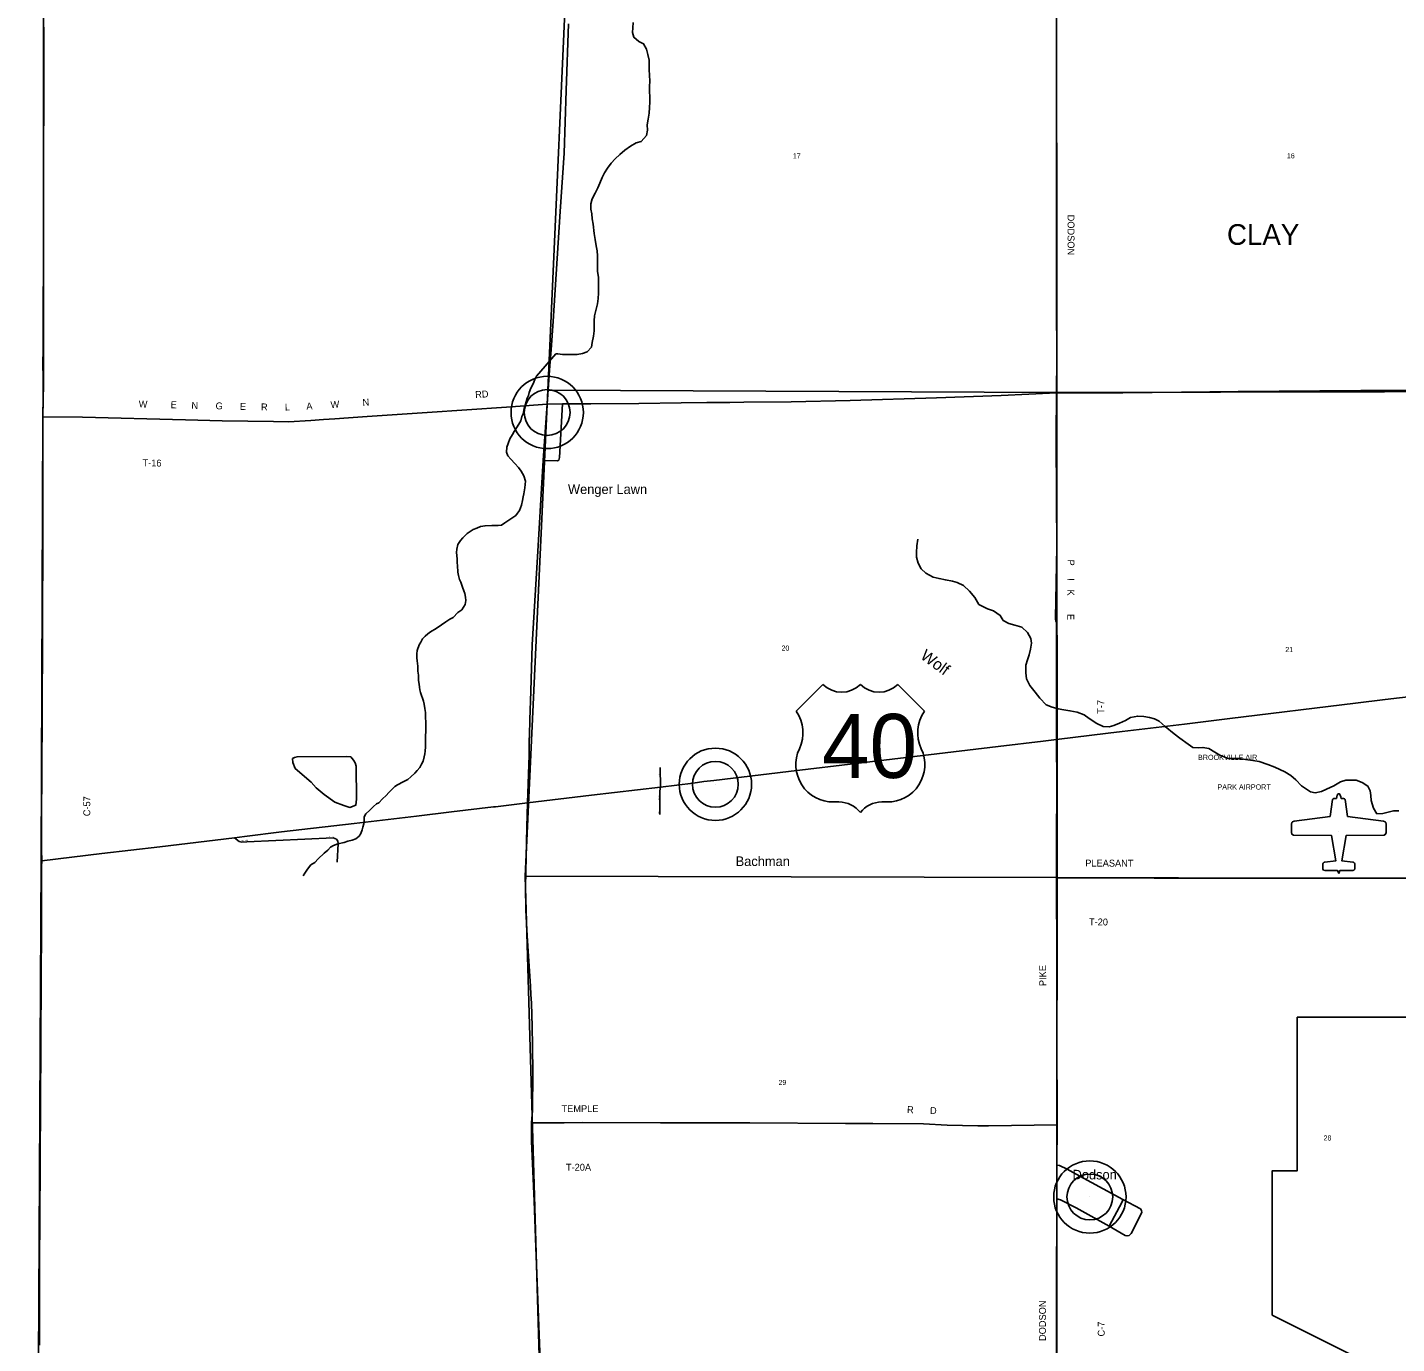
# Model space of a CAD drawing. Extents: x 1312308 to 1684953, y 460642 to 865172.
# Drawn here: x 1411378 to 1426256, y 678293 to 692598 of the extents above; entities that cross this region are included whole.
import ezdxf

# ---------------------------------------------------------------- set-up
doc = ezdxf.new("R2010")
doc.units = 0
for name, color, linetype in [('GM_X_Adjacent_County', 7, 'Continuous'), ('GM_X_Airport_Class_3', 7, 'Continuous'), ('GM_X_Airport_Location_Class_3', 7, 'Continuous'), ('GM_X_Airport_Text_Class_3', 7, 'Continuous'), ('GM_X_Corporation', 7, 'Continuous'), ('GM_X_County', 7, 'Continuous'), ('GM_X_County_Road', 7, 'Continuous'), ('GM_X_County_Road_Text', 7, 'Continuous'), ('GM_X_Minor_Lake', 7, 'Continuous'), ('GM_X_Minor_River', 7, 'Continuous'), ('GM_X_Minor_River_Text', 7, 'Continuous'), ('GM_X_Section', 7, 'Continuous'), ('GM_X_Section_Text', 7, 'Continuous'), ('GM_X_Township', 7, 'Continuous'), ('GM_X_Township_Road', 7, 'Continuous'), ('GM_X_Township_Road_Text', 7, 'Continuous'), ('GM_X_Township_Subdivision', 7, 'Continuous'), ('GM_X_Township_Subdivision_Text', 7, 'Continuous'), ('GM_X_Township_Text', 7, 'Continuous'), ('GM_X_Unincorporated', 7, 'Continuous'), ('GM_X_Unincorporated_Location', 7, 'Continuous'), ('GM_X_Unincorporated_Text', 7, 'Continuous'), ('GM_X_US_Location', 7, 'Continuous'), ('GM_X_US_Route', 7, 'Continuous'), ('GM_X_US_Shield', 7, 'Continuous')]:
    doc.layers.add(name, color=color, linetype=linetype)

msp = doc.modelspace()

# ---------------------------------------------------------------- linework, layer by layer
at = {"layer": 'GM_X_Adjacent_County'}
msp.add_lwpolyline([(1411554, 694026), (1411551, 688725), (1411547, 688368), (1411526, 683541), (1411498, 678086), (1411466, 675468), (1411467, 672788), (1411460, 671583), (1411440, 668150), (1411439, 668011), (1411421, 665395), (1411387, 659976), (1411378, 657454)], dxfattribs=at)
at = {"layer": 'GM_X_Airport_Class_3'}
for points in [[(1425628, 684270), (1425621, 684267), (1425612, 684255), (1425606, 684237), (1425603, 684219), (1425576, 684219), (1425566, 684215), (1425560, 684207), (1425534, 684023), (1425142, 683973), (1425125, 683965), (1425119, 683958), (1425113, 683940), (1425113, 683849), (1425119, 683830), (1425136, 683818), (1425549, 683815), (1425597, 683541), (1425475, 683527), (1425468, 683525), (1425457, 683516), (1425454, 683509), (1425453, 683459), (1425454, 683451), (1425463, 683439), (1425478, 683434), (1425615, 683434), (1425628, 683402)], [(1425628, 683402), (1425641, 683434), (1425779, 683434), (1425793, 683439), (1425802, 683451), (1425803, 683459), (1425802, 683509), (1425799, 683516), (1425788, 683525), (1425781, 683527), (1425660, 683541), (1425708, 683815), (1426121, 683818), (1426137, 683830), (1426144, 683849), (1426143, 683940), (1426138, 683958), (1426132, 683965), (1426114, 683973), (1425723, 684023), (1425696, 684207), (1425691, 684215), (1425680, 684219), (1425653, 684219), (1425650, 684237), (1425644, 684255), (1425636, 684267), (1425628, 684270)]]:
    msp.add_lwpolyline(points, dxfattribs=at)
at = {"layer": 'GM_X_Airport_Location_Class_3'}
msp.add_line((1425628, 683860), (1425628, 683860), dxfattribs=at)
at = {"layer": 'GM_X_Corporation'}
msp.add_lwpolyline([(1426321, 678047), (1426075, 678047), (1425962, 678149), (1425788, 678160), (1424905, 678604), (1424905, 680172), (1425177, 680172), (1425176, 681841), (1427466, 681840)], dxfattribs=at)
at = {"layer": 'GM_X_County'}
msp.add_lwpolyline([(1411378, 657454), (1411387, 659976), (1411421, 665395), (1411439, 668011), (1411440, 668150), (1411460, 671583), (1411467, 672788), (1411466, 675468), (1411498, 678086), (1411526, 683541), (1411547, 688368), (1411551, 688725), (1411554, 694026)], dxfattribs=at)
at = {"layer": 'GM_X_County_Road'}
for points in [[(1416954, 678016), (1416921, 678865), (1416904, 679342), (1416884, 679840), (1416856, 680494), (1416857, 680694), (1416867, 680827), (1416869, 681236), (1416866, 681531), (1416864, 681740), (1416855, 681993), (1416850, 682089), (1416844, 682179), (1416826, 682450), (1416809, 682724), (1416794, 683003), (1416790, 683256), (1416805, 683906), (1416814, 684171), (1416830, 684687), (1416832, 684851), (1416834, 684906), (1416838, 685073), (1416848, 685386), (1416862, 685889), (1416921, 686846), (1416975, 687772), (1416984, 687890), (1416999, 688152), (1417026, 688504), (1417056, 688924), (1417068, 689094), (1417090, 689407), (1417166, 690597), (1417211, 691233), (1417234, 691914), (1417256, 692638)], [(1411534, 683542), (1411534, 683558), (1411534, 683572), (1411533, 683593), (1411532, 683603), (1411532, 683612), (1411532, 683650), (1411532, 683849), (1411532, 684007), (1411532, 684205), (1411533, 684324), (1411534, 684491), (1411535, 684644), (1411536, 684758), (1411537, 684895), (1411538, 685152), (1411538, 685253), (1411539, 685348), (1411540, 685495), (1411541, 685644), (1411541, 685704), (1411542, 685861), (1411543, 686072), (1411542, 686278), (1411543, 686478), (1411544, 686686), (1411544, 686837), (1411544, 687002), (1411544, 687046), (1411544, 687232), (1411545, 687436), (1411544, 687738), (1411544, 687910), (1411544, 688155), (1411546, 688367), (1411546, 688397), (1411548, 688552), (1411548, 688664), (1411548, 688727), (1411548, 688761), (1411547, 688974), (1411548, 689064), (1411548, 689266), (1411549, 689464), (1411550, 689735), (1411551, 689836), (1411552, 690019), (1411553, 690157), (1411553, 690277), (1411554, 690473), (1411554, 690678), (1411554, 690772), (1411554, 690891), (1411554, 690991), (1411553, 691150), (1411553, 691262), (1411553, 691405), (1411555, 691648), (1411556, 691810), (1411556, 691982), (1411556, 692267), (1411556, 692344), (1411556, 692426), (1411557, 692600)], [(1422561, 683356), (1422561, 683745), (1422563, 684363), (1422562, 684860)], [(1411508, 678276), (1411508, 678436), (1411508, 678468), (1411509, 678624), (1411509, 678699), (1411509, 678914), (1411509, 679044), (1411510, 679143), (1411511, 679294), (1411512, 679543), (1411513, 679697), (1411514, 679883), (1411515, 680024), (1411516, 680191), (1411517, 680321), (1411518, 680450), (1411518, 680561), (1411519, 680637), (1411520, 680844), (1411521, 681029), (1411522, 681181), (1411523, 681276), (1411523, 681382), (1411524, 681488), (1411524, 681664), (1411525, 681773), (1411525, 681880), (1411526, 681953), (1411526, 682098), (1411527, 682209), (1411528, 682283), (1411529, 682459), (1411530, 682607), (1411531, 682803), (1411532, 682960), (1411532, 683172), (1411532, 683291), (1411532, 683447), (1411532, 683473), (1411532, 683488), (1411532, 683495), (1411532, 683501), (1411532, 683508), (1411533, 683515), (1411533, 683524), (1411534, 683542)], [(1422564, 678007), (1422566, 678768), (1422564, 679455), (1422563, 679532), (1422566, 679868), (1422566, 680232), (1422568, 680673), (1422566, 681655), (1422564, 682449), (1422561, 683356)]]:
    msp.add_lwpolyline(points, dxfattribs=at)
at = {"layer": 'GM_X_Minor_Lake'}
for points in [[(1414954, 684212), (1414952, 684571), (1414940, 684604), (1414921, 684636), (1414892, 684669), (1414841, 684676), (1414309, 684672), (1414281, 684664), (1414259, 684651), (1414262, 684610), (1414288, 684544)], [(1414288, 684544), (1414460, 684394), (1414517, 684334), (1414601, 684260), (1414718, 684179), (1414816, 684143), (1414883, 684120), (1414946, 684144), (1414954, 684212)]]:
    msp.add_lwpolyline(points, dxfattribs=at)
at = {"layer": 'GM_X_Minor_River'}
for points in [[(1417962, 692651), (1417956, 692595), (1417954, 692541), (1417966, 692491), (1418022, 692446), (1418074, 692420), (1418104, 692361), (1418121, 692302), (1418133, 692243), (1418133, 692189), (1418135, 692133), (1418139, 692082), (1418140, 692012), (1418138, 691958), (1418138, 691906), (1418140, 691840), (1418140, 691785), (1418139, 691727), (1418133, 691665), (1418123, 691601), (1418112, 691539), (1418116, 691481), (1418106, 691425), (1418047, 691357), (1417994, 691343), (1417932, 691307), (1417870, 691264), (1417814, 691218), (1417764, 691171), (1417720, 691121), (1417682, 691070), (1417649, 691017), (1417623, 690966), (1417597, 690905), (1417577, 690853), (1417546, 690798), (1417516, 690735), (1417502, 690681), (1417501, 690621), (1417512, 690571), (1417515, 690516), (1417525, 690460), (1417538, 690359), (1417549, 690294), (1417558, 690224), (1417570, 690169), (1417572, 690117), (1417574, 690060), (1417572, 689998), (1417574, 689946), (1417582, 689885), (1417585, 689821), (1417585, 689767), (1417583, 689709), (1417579, 689653), (1417572, 689595), (1417541, 689465), (1417535, 689409), (1417537, 689351), (1417535, 689299), (1417529, 689241), (1417516, 689175), (1417506, 689123), (1417462, 689071), (1417409, 689055), (1417352, 689045), (1417298, 689045), (1417243, 689043), (1417191, 689045), (1417141, 689051), (1417119, 689052)], [(1417119, 689052), (1416910, 688809), (1416893, 688771), (1416872, 688724), (1416848, 688676), (1416831, 688631), (1416822, 688597), (1416808, 688567), (1416792, 688505), (1416781, 688473), (1416764, 688400), (1416749, 688368), (1416738, 688324), (1416717, 688285), (1416694, 688245), (1416669, 688208), (1416648, 688172), (1416621, 688125), (1416601, 688075), (1416586, 688035), (1416583, 687981), (1416600, 687943), (1416631, 687906), (1416674, 687859), (1416713, 687814), (1416744, 687775), (1416771, 687724), (1416790, 687668), (1416784, 687594), (1416772, 687530), (1416766, 687498), (1416759, 687456), (1416747, 687406), (1416737, 687376), (1416724, 687349), (1416705, 687319), (1416684, 687292), (1416652, 687272), (1416609, 687243), (1416566, 687212), (1416528, 687187), (1416494, 687186), (1416455, 687185), (1416423, 687184), (1416351, 687182), (1416303, 687173), (1416260, 687154), (1416222, 687143), (1416155, 687098), (1416108, 687049), (1416085, 687022), (1416056, 686978), (1416045, 686927), (1416042, 686893), (1416043, 686857), (1416048, 686818), (1416049, 686778), (1416052, 686750), (1416056, 686678), (1416064, 686640), (1416075, 686599), (1416086, 686569), (1416107, 686516), (1416120, 686474), (1416131, 686446), (1416140, 686407), (1416143, 686371), (1416134, 686325), (1416097, 686268), (1416054, 686241), (1416004, 686184), (1415970, 686167), (1415923, 686138), (1415878, 686105), (1415819, 686067), (1415758, 686030), (1415730, 686007), (1415701, 685981), (1415672, 685954), (1415653, 685918), (1415635, 685887), (1415615, 685827), (1415608, 685791), (1415609, 685747), (1415612, 685713), (1415619, 685655), (1415622, 685603), (1415627, 685558), (1415629, 685502), (1415634, 685462), (1415639, 685428), (1415643, 685400), (1415650, 685371), (1415661, 685337), (1415670, 685309), (1415682, 685274), (1415689, 685244), (1415698, 685196), (1415703, 685152), (1415705, 685092), (1415706, 685053)], [(1426042, 684051), (1426004, 684112), (1425979, 684195), (1425977, 684251), (1425968, 684301), (1425945, 684352), (1425881, 684391), (1425818, 684417), (1425761, 684416), (1425703, 684417), (1425647, 684399), (1425573, 684356), (1425496, 684318), (1425439, 684295), (1425371, 684280), (1425319, 684289), (1425222, 684354), (1425161, 684419), (1425106, 684467), (1425043, 684506), (1424989, 684532), (1424933, 684557), (1424858, 684587), (1424762, 684621), (1424694, 684632), (1424614, 684642), (1424544, 684652), (1424427, 684654), (1424334, 684689), (1424280, 684720), (1424217, 684761), (1424151, 684773), (1424101, 684768), (1424043, 684773), (1423991, 684809), (1423902, 684873), (1423841, 684920), (1423742, 684999), (1423676, 685058), (1423624, 685082), (1423572, 685097), (1423510, 685108), (1423444, 685114), (1423365, 685097), (1423310, 685065), (1423245, 685036), (1423183, 685011), (1423132, 684996), (1423066, 685000), (1423000, 685033), (1422917, 685087), (1422862, 685127), (1422784, 685157), (1422706, 685172), (1422642, 685182), (1422578, 685193), (1422512, 685209), (1422447, 685234), (1422380, 685310), (1422327, 685373), (1422271, 685447), (1422234, 685518), (1422228, 685584), (1422229, 685668), (1422247, 685726), (1422264, 685780), (1422279, 685840), (1422289, 685906), (1422282, 685958), (1422247, 686021), (1422184, 686079), (1422107, 686100), (1422043, 686118), (1421981, 686153), (1421950, 686208), (1421875, 686256), (1421809, 686280), (1421716, 686328), (1421672, 686401), (1421615, 686470), (1421550, 686534), (1421480, 686566), (1421429, 686579), (1421353, 686593), (1421285, 686608), (1421219, 686624), (1421141, 686665), (1421090, 686713), (1421059, 686776), (1421041, 686840), (1421040, 686892), (1421044, 686964), (1421053, 687035)], [(1415706, 685053), (1415707, 684997), (1415703, 684849), (1415704, 684781), (1415700, 684733), (1415698, 684703), (1415691, 684671), (1415678, 684623), (1415659, 684592), (1415644, 684556), (1415613, 684521), (1415588, 684493), (1415545, 684452), (1415511, 684425), (1415460, 684398), (1415401, 684368), (1415371, 684348), (1415342, 684319), (1415305, 684284), (1415276, 684250), (1415237, 684215), (1415198, 684172), (1415170, 684159), (1415139, 684132), (1415098, 684091), (1415055, 684050), (1415036, 684018), (1415037, 683990), (1415032, 683942), (1415023, 683908), (1415017, 683878), (1415000, 683838), (1414983, 683809), (1414948, 683780), (1414908, 683765), (1414861, 683754), (1414821, 683741), (1414750, 683724), (1414704, 683708), (1414673, 683688), (1414641, 683657), (1414602, 683622), (1414538, 683563), (1414501, 683524), (1414459, 683497), (1414434, 683466), (1414413, 683438), (1414394, 683407), (1414374, 683379)], [(1426280, 684084), (1426224, 684085), (1426107, 684055), (1426042, 684051)]]:
    msp.add_lwpolyline(points, dxfattribs=at)
at = {"layer": 'GM_X_Section'}
for points in [[(1417275, 694064), (1422559, 694065), (1422564, 688632), (1417033, 688657)], [(1422559, 694065), (1427905, 694068), (1427903, 688640), (1422564, 688632)], [(1422564, 688632), (1422569, 683358), (1416787, 683374), (1417033, 688657)], [(1422564, 688632), (1427903, 688640), (1427845, 683343), (1422569, 683358)], [(1422560, 678014), (1416942, 678035), (1416787, 683374), (1422569, 683358)], [(1422569, 683358), (1427845, 683343), (1428048, 678006), (1422560, 678014)]]:
    msp.add_lwpolyline(points, close=True, dxfattribs=at)
at = {"layer": 'GM_X_Township'}
msp.add_lwpolyline([(1427419, 672761), (1424384, 672755), (1422900, 672752), (1422582, 672753), (1420996, 672758), (1419372, 672773), (1417662, 672772), (1417276, 672769), (1416556, 672769), (1415857, 672775), (1415014, 672778), (1414138, 672775), (1411467, 672788), (1411466, 675468), (1411498, 678086), (1411526, 683541), (1411547, 688368), (1411551, 688725), (1411554, 694026)], dxfattribs=at)
at = {"layer": 'GM_X_Township_Road'}
for points in [[(1422562, 684860), (1422562, 685147), (1422560, 685991), (1422562, 686129), (1422552, 686148), (1422549, 686165), (1422549, 686178), (1422564, 686948), (1422560, 687475), (1422558, 688147), (1422561, 688626), (1422564, 689001), (1422560, 689600), (1422560, 690735), (1422559, 691933), (1422560, 692689), (1422559, 694054)], [(1417026, 688504), (1417194, 688506), (1417499, 688508), (1418021, 688512), (1418481, 688517), (1418762, 688521), (1419011, 688521), (1419164, 688524), (1419677, 688530), (1420319, 688545), (1421255, 688573), (1421959, 688598), (1422561, 688626)], [(1422561, 688626), (1423282, 688627), (1423920, 688635), (1424533, 688641), (1425866, 688653), (1426538, 688652), (1427912, 688658)], [(1411546, 688367), (1411978, 688361), (1413097, 688334), (1413493, 688324), (1414051, 688314), (1414215, 688312), (1414457, 688325), (1414594, 688336), (1414717, 688344), (1414867, 688354), (1415069, 688368), (1415721, 688413), (1416585, 688472), (1417026, 688504)], [(1422561, 683356), (1423622, 683353), (1425225, 683352), (1426659, 683351), (1427558, 683351), (1427848, 683350)], [(1416857, 680694), (1417210, 680694), (1417406, 680695), (1418256, 680694), (1419229, 680694), (1420269, 680687), (1420564, 680684), (1421116, 680682), (1421372, 680668), (1421705, 680659), (1421821, 680660), (1422568, 680673)]]:
    msp.add_lwpolyline(points, dxfattribs=at)
at = {"layer": 'GM_X_Township_Subdivision'}
for points in [[(1416984, 687890), (1417140, 687886), (1417152, 687896), (1417161, 687924), (1417194, 688506)], [(1418252, 684300), (1418257, 684342), (1418255, 684556)], [(1418249, 684044), (1418252, 684300), (1418252, 684300)], [(1413630, 683792), (1413680, 683752), (1413708, 683745), (1413761, 683746), (1414394, 683775), (1414700, 683789), (1414735, 683776), (1414751, 683755), (1414754, 683729), (1414744, 683526)], [(1422566, 679868), (1422605, 679857), (1422774, 679768), (1423133, 679570), (1423307, 679470), (1423328, 679464), (1423351, 679469), (1423371, 679491), (1423487, 679720), (1423485, 679739), (1423472, 679757), (1423280, 679860), (1422941, 680046), (1422776, 680136), (1422676, 680190), (1422594, 680230), (1422566, 680232)], [(1423133, 679570), (1423273, 679836), (1423280, 679860)]]:
    msp.add_lwpolyline(points, dxfattribs=at)
at = {"layer": 'GM_X_Unincorporated'}
for centre, radius in [((1417026, 688413), 393), ((1417026, 688413), 249), ((1418854, 684372), 393), ((1418854, 684372), 249), ((1422923, 679887), 393), ((1422923, 679887), 249)]:
    msp.add_circle(centre, radius, dxfattribs=at)
at = {"layer": 'GM_X_Unincorporated_Location'}
for p, q in [((1417026, 688413), (1417026, 688413)), ((1418854, 684372), (1418854, 684372)), ((1422923, 679887), (1422923, 679887))]:
    msp.add_line(p, q, dxfattribs=at)
at = {"layer": 'GM_X_US_Route'}
for points in [[(1418729, 684401), (1418837, 684415), (1419650, 684513), (1420442, 684604), (1421925, 684782), (1422417, 684842), (1422562, 684860), (1423121, 684928), (1423273, 684945), (1423952, 685026), (1424444, 685087), (1425810, 685253), (1426133, 685294), (1426536, 685340)], [(1416442, 684126), (1416463, 684129), (1416814, 684171), (1417509, 684254), (1418257, 684342), (1418612, 684386), (1418729, 684401)], [(1413736, 683805), (1414140, 683854), (1414930, 683946), (1415606, 684027), (1415988, 684072), (1416442, 684126)], [(1411534, 683542), (1412186, 683619), (1412818, 683691), (1413630, 683792), (1413736, 683805)]]:
    msp.add_lwpolyline(points, dxfattribs=at)
at = {"layer": 'GM_X_US_Shield'}
for p, q in [((1420023, 685456), (1419733, 685166)), ((1421125, 685166), (1420835, 685456)), ((1420139, 684180), (1420197, 684180)), ((1420661, 684180), (1420719, 684180))]:
    msp.add_line(p, q, dxfattribs=at)
for centre, radius, start, end in [((1420226, 685663), 290, 225.573, 314.427), ((1420632, 685663), 290, 225.573, 314.427), ((1419400, 684933), 406, 334.5471, 35.0009), ((1421458, 684933), 406, 144.9991, 205.4529), ((1420134, 684586), 406, 154.8319, 270.6383), ((1420724, 684586), 406, 269.3617, 25.1681), ((1420197, 683890), 290, 36.8699, 90), ((1420661, 683890), 290, 90, 143.1301)]:
    msp.add_arc(centre, radius, start, end, dxfattribs=at)

# ---------------------------------------------------------------- texts
at = {"layer": 'GM_X_Airport_Text_Class_3'}
for s, p in [('BROOKVILLE AIR', (1424099, 684637)), ('PARK AIRPORT', (1424310, 684315))]:
    msp.add_text(s, height=56.25, rotation=0, dxfattribs=at).set_placement(p)
at = {"layer": 'GM_X_County_Road_Text'}
for s, rotation, p in [('C-57', 89.8108, (1412061, 684025)), ('PIKE', 90.309, (1422449, 682179)), ('DODSON', 89.835, (1422445, 678322)), ('C-7', 90, (1423084, 678371))]:
    msp.add_text(s, height=75, rotation=rotation, dxfattribs=at).set_placement(p)
at = {"layer": 'GM_X_Minor_River_Text'}
msp.add_text('Wolf', height=125, rotation=323.8551, dxfattribs=at).set_placement((1421072, 685746))
at = {"layer": 'GM_X_Section_Text'}
for s, p in [('17', (1419696, 691174)), ('16', (1425064, 691175)), ('20', (1419573, 685825)), ('21', (1425047, 685809)), ('29', (1419540, 681104)), ('28', (1425463, 680501))]:
    msp.add_text(s, height=55.3, rotation=0, dxfattribs=at).set_placement(p)
at = {"layer": 'GM_X_Township_Road_Text'}
for s, rotation, p in [('DODSON', 270, (1422681, 690563)), ('RD', 3.9111, (1416246, 688569)), ('W', 358.611, (1412587, 688468)), ('E', 358.6071, (1412934, 688460)), ('N', 358.6122, (1413159, 688454)), ('G', 358.6083, (1413422, 688448)), ('E', 358.6172, (1413686, 688442)), ('R', 359.5005, (1413916, 688436)), ('L', 2.062, (1414177, 688434)), ('A', 3.8134, (1414411, 688443)), ('W', 3.905, (1414675, 688460)), ('N', 3.9045, (1415022, 688484)), ('T-16', 358.5864, (1412628, 687830)), ('P', 269.6959, (1422681, 686815)), ('I', 269.6996, (1422680, 686613)), ('K', 269.7055, (1422679, 686489)), ('E', 269.9672, (1422678, 686224)), ('T-7', 90, (1423079, 685138)), ('PLEASANT', 359.732, (1422873, 683479)), ('T-20', 359.2915, (1422913, 682840)), ('TEMPLE', 0, (1417182, 680809)), ('R', 357.7201, (1420935, 680800)), ('D', 358.3674, (1421185, 680790)), ('T-20A', 0, (1417230, 680173))]:
    msp.add_text(s, height=75, rotation=rotation, dxfattribs=at).set_placement(p)
at = {"layer": 'GM_X_Township_Subdivision_Text'}
for s, rotation, p in [('ST', 90, (1418246, 684474)), ('NAME', 90, (1418246, 684201)), ('NO', 90, (1418246, 684056)), ('ACCESS', 3.238, (1413705, 683753)), ('R', 357.7895, (1414656, 683797)), ('D', 344.8053, (1414692, 683796))]:
    msp.add_text(s, height=12.5, rotation=rotation, dxfattribs=at).set_placement(p)
at = {"layer": 'GM_X_Township_Text'}
msp.add_text('CLAY', height=225, rotation=0, dxfattribs=at).set_placement((1424413, 690235))
at = {"layer": 'GM_X_Unincorporated_Text'}
for s, height, p in [('Wenger Lawn', 104.25, (1417252, 687527)), ('Bachman', 104.3, (1419074, 683484)), ('Dodson', 104.3, (1422735, 680078))]:
    msp.add_text(s, height=height, rotation=0, dxfattribs=at).set_placement(p)
at = {"layer": 'GM_X_US_Location'}
for s in ['0', '/']:
    msp.add_text(s, height=0.25, dxfattribs=at).set_placement((1420429, 684784))
msp.add_text('40', height=0.25, rotation=0, dxfattribs=at).set_placement((1420222, 684577))
at = {"layer": 'GM_X_US_Shield'}
msp.add_text('40', height=696.1, dxfattribs=at).set_placement((1420011, 684441))

doc.saveas('drawing.dxf')
